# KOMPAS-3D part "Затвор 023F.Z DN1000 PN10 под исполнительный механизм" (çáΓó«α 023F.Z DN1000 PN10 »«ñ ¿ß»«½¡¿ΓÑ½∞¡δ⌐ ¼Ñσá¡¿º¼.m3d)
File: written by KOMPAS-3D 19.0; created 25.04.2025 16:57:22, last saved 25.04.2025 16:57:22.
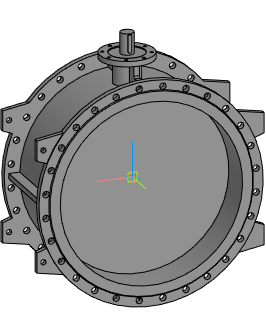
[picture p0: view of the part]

Document properties: Автор: Евгений; Полное имя файла: E:\Dendor Работа Сачек\3D для проекитирвщиков\1.7 Тип 023F.Z Затвор дисковый поворотный фланцевый с двумя эксцентриками\stp_Тип 023F.Z. Затвор под исполн. механизм\Затвор 023F.Z DN1000 PN10 под исполнительный механизм.m3d

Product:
- Part/product: Затвор 023F.Z DN1000 PN10 под исполнительный механизм

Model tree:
1. Операция без истории:1  (labels: Затвор 023F.Z DN1000 PN10 под исполнительный механизм)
